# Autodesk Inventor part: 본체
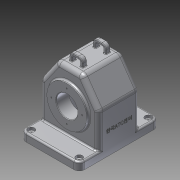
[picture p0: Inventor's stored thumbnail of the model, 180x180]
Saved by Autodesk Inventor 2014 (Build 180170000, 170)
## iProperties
Created: 2016-12
Part Number: 본체
Material: 알루미늄 6061
Document SubType Name: Modeling
Designer: USER
Density: 2.71 g/cm^3
Appearance: 알루미늄 - 평지
Mass: 1064.13 g
Surface Area: 1148.12 cm^2
Volume: 392.67 cm^3
Author: USER
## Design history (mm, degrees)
sketch "스케치1"
  geometry: L1 (-55, 0)-(-23.491, 45); L2 (-23.491, 45)-(23.491, 45); L3 (23.491, 45)-(55, 0); L4 (55, 0)-(55, -80); L5 (55, -80)-(-55, -80); L6 (-55, -80)-(-55, 0); 3 further points
  constraints: 12 end point, 2 midpoint, 2 perpendicular, 2 vertical alignment, 1 horizontal, 1 horizontal alignment, 1 parallel
  dimensions: "d1" = 125 distance between parallel lines of L5 L2; "d2" = 80 distance of L4.end L3.end; "d3" = 80 distance of L5.end L1.start; "d4" = 110 distance of L4.end L5.end; "d5" = 35 deg angle of L6 L1
extrude "돌출1" new body sketch "스케치1" stored distance "d6" = 77; taper "d7" = 0 deg
feature "쉘1" dims "d13" = 5
sketch "스케치5"
  geometry: L1 (-55, -80)-(55, -80) reference; C1 r 37.5 at (0, -15); 1 further point
  constraints: 1 centre point, 1 vertical alignment
  dimensions: "d14" = 75 diameter of C1; "d15" = 65 distance from line of L1 C1.centre
extrude "돌출3" join sketch "스케치5" distance "d16" = 5; taper "d17" = 0 deg
sketch "스케치6"
  geometry: L1 (0, 0)-(100, 0) reference; C1 r 27 at (50, -65); 1 further point
  constraints: 1 centre point, 1 vertical alignment
  dimensions: "d18" = 54 diameter of C1; "d19" = 65 distance from line of L1 C1.centre
extrude "돌출4" join sketch "스케치6" distance "d20" = 14; taper "d21" = 0 deg
sketch "스케치7"
  geometry: L1 (-33.5, 12)-(-19.5, 12) reference; L2 (-33.5, 40)-(-33.5, -1.576) reference; L3 (0, -15)-(-58.229, -15); L4 (33.5, -80)-(-33.5, -80) reference; L5 (-19.5, 12)-(-33.5, 26); L6 (-19.5, -42)-(-19.5, 12) reference; 1 further point
  constraints: 4 end point, 1 perpendicular, 1 point on line
  dimensions: "d22" = 65 distance from line of L4 L3.start; "d23" = 45 deg angle of L6 L5
revolve "회전1" sketch "스케치7" stored, may be unused: angle "d24" = 90 deg
sketch "스케치8"
  geometry: C1 r 37.5 at (0, 0) reference; C2 r 20 at (0, 0); 1 further point
  constraints: 1 centre point, 1 coincident
  dimensions: "d25" = 40 diameter of C2
extrude "돌출5" cut sketch "스케치8" distance "d26" = 24; taper "d27" = 0 deg
sketch "스케치9" dims "d28" = 58
  geometry: C1 r 37.5 at (0, 0) reference; 3 further points
  constraints: 2 vertical alignment, 1 coincident, 2 other
hole "구멍1" sketch "스케치9" at (0, 29) diameter "d29" = 2.459; stored, may be unused: countersink angle "d33" = 90 deg, drill point angle "d35" = 118 deg; dims "d30" = 6, "d31" = 4, "d32" = 2, "d34" = 8
sketch "스케치10"
  geometry: L1 (55, 80)-(-55, 80) reference; C1 r 31 at (0, 15); 1 further point
  constraints: 1 centre point, 1 vertical alignment
  dimensions: "d39" = 62 diameter of C1; "d40" = 65 distance from line of L1 C1.centre
extrude "돌출6" join sketch "스케치10" distance "d41" = 10; taper "d42" = 0 deg
sketch "스케치11"
  geometry: C1 r 31 at (0, 0) reference; C2 r 20 at (0, 0); 1 further point
  constraints: 1 centre point, 1 coincident
  dimensions: "d43" = 40 diameter of C2
extrude "돌출7" cut sketch "스케치11" distance "d44" = 15; taper "d45" = 0 deg
sketch "스케치12" dims "d46" = 52
  geometry: C1 r 20 at (0, 0) reference; C2 r 31 at (0, 0) reference; 3 further points
  constraints: 2 vertical alignment, 1 coincident, 2 other
hole "구멍2" sketch "스케치12" at (0, 26) diameter "d47" = 2.459; stored, may be unused: countersink angle "d51" = 90 deg, drill point angle "d53" = 118 deg; dims "d48" = 6, "d49" = 4, "d50" = 2, "d52" = 8
fillet "모깎기1" dims "d57" = 10
sketch "스케치13"
  geometry: L1 (110, 0)-(110, -77) reference; L2 (0, 0)-(110, 0) reference; L3 (0, 0)-(0, -77) reference; L4 (110, -77)-(0, -77) reference; L5 (0, 36.5)-(110, 36.5); L6 (110, 36.5)-(110, -113.5); L7 (110, -113.5)-(0, -113.5); L8 (0, -113.5)-(0, 36.5); 3 further points
  constraints: 8 end point, 2 midpoint, 2 parallel, 1 horizontal, 1 horizontal alignment, 1 perpendicular, 1 vertical alignment
  dimensions: "d58" = 150 distance of L5.end L6.end; "d59" = 110 distance of L5.start L5.end
extrude "돌출8" join sketch "스케치13" distance "d60" = 15; taper "d61" = 0 deg
fillet "모깎기2" dims "d62" = 10
sketch "스케치14"
  geometry: C1 r 6 at (-100, -103.5); A1 r 10 centre (-100, -103.5) between (-110, -103.5) and (-100, -113.5) reference; 1 further point
  constraints: 1 centre point, 1 coincident
  dimensions: "d63" = 12 diameter of C1
extrude "돌출9" cut sketch "스케치14" distance "d64" = 5; taper "d65" = 0 deg
sketch "스케치15"
  geometry: C1 r 6 at (0, 0) reference; C2 r 2.5 at (0, 0); 1 further point
  constraints: 1 centre point, 1 coincident
  dimensions: "d66" = 5 diameter of C2
extrude "돌출10" cut sketch "스케치15" distance "d67" = 10; taper "d68" = 0 deg
fillet "모깎기3" dims "d69" = 3
fillet "모깎기4" dims "d70" = 3
fillet "모깎기5" dims "d71" = 8
fillet "모깎기6" dims "d72" = 3
fillet "모깎기7" dims "d73" = 3
node "작업 평면1"
sketch "스케치16"
  geometry: L1 (18.285, 45)-(-18.285, 45) reference; L2 (-12.5, 45)-(-12.5, 60); L3 (-12.5, 60)-(12.5, 60); L4 (12.5, 60)-(12.5, 45); L5 (-7.5, 45)-(-7.5, 55); L6 (-7.5, 55)-(7.5, 55); L7 (7.5, 55)-(7.5, 45); L8 (-45, -80)-(45, -80) reference; 3 further points
  constraints: 12 end point, 5 perpendicular, 4 point on line, 2 midpoint, 2 vertical alignment, 1 parallel
  dimensions: "d75" = 5 distance between parallel lines of L6 L3; "d76" = 25 distance of L2.end L3.end; "d77" = 15 distance between parallel lines of L7 L5; "d78" = 140 distance between parallel lines of L8 L3
extrude "돌출11" join sketch "스케치16" stored distance "d79" = 8; taper "d80" = 0 deg
fillet "모깎기8" dims "d81" = 8
fillet "모깎기9" dims "d82" = 3
fillet "모깎기10" dims "d83" = 8
fillet "모깎기11" dims "d84" = 3
fillet "모깎기12" dims "d85" = 1
fillet "모깎기13" dims "d86" = 1
fillet "모깎기14" dims "d87" = 1
fillet "모깎기15" dims "d88" = 1
sketch "스케치17"
  geometry: L1 (0, 130)-(0, 0) reference; L2 (-76.847, 26.5)-(-18, 26.5) reference; 2 further points
  constraints: 1 other
  dimensions: "d89" = 45 distance from line of L1 point (-45, 65); "d90" = 38.5 distance from line of L2 point (-45, 65)
feature "엠보싱1" sketch "스케치17" dims "d91" = 0.5, "d92" = 0
chamfer "모따기1" distance "d95" = 1; stored, may be unused: second distance "d96" = 2, angle "d97" = 45 deg
fillet "모깎기18" dims "d98" = 3
node "솔리드1"
pattern_circular "원형 패턴1" dims angle "d37" = 360 deg
pattern_circular "원형 패턴2" dims angle "d55" = 360 deg
mirror "대칭1"
mirror "대칭2"
mirror "대칭3"
other parameters: "d74" = 22
